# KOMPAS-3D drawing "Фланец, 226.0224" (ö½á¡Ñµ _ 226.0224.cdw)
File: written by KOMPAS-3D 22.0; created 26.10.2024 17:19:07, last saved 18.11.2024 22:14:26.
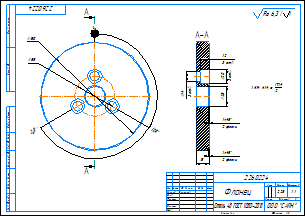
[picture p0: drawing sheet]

Sheet 1: A3, landscape

Document properties: Автор: aleksander.larionov.10@gmail.com; Полное имя файла: C:\Мои папки\Работа\Крышки, фланцы\226.0224\Фланец _ 226.0224.cdw; Знак неуказанной шероховатости: 4; Параметр неуказанной шероховатости: Ra 6,3; Масса: 2.283354

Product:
- Part/product: Фланец  | designation 226.0224
    Материал: Сталь 45 ГОСТ 1050-2013 (density 7810 kg/m3)
    Масса: 2.283354

Title block, sheet 1: Наименование: Фланец; designation: 226.0224; Материал: Сталь 45 ГОСТ 1050-2013; Масса: 2,28; Количество листов документа: 1; organisation: ООО "САЙН"; Форматы листов документа: A3; stored path: C:\Users\aleks\Desktop\Работа\226.0224\Фланец _ 226.0224.cdw; Разработал: Ларионов

Views: Вид 1, Сверху, Разрез А-А
Referenced files in C:\Users\aleks\Desktop\Работа\226.0224\: Фланец _ 226.0224.m3d
Referenced files in C:\Мои папки\Работа\Крышки, фланцы\226.0224\: Фланец _ 226.0224.m3d
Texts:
  Ra 6,3
  Ra 6,3 ( )
Dimensions and other numbers on the sheet: 120; 240; 150; 55; 226.0224; 5; 18; 28; 1; 2 фаски; 20; 3 отв.; 14; 12; 1 H14, h14,    IT14 2 .; 6; 1:1; 2,28; 226.0224 Фланец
